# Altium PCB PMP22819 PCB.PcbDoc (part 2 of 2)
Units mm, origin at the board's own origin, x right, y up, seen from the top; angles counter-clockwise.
Board outline 101.6 x 76.2 mm, 4 copper layers (Top Layer, Mid-Layer 1, Mid-Layer 2, Bottom Layer), stack 2.286 mm thick; 108 components, 51 nets, 288 pads, 278 vias.
Unrouted connection lines stored in the file: 1.
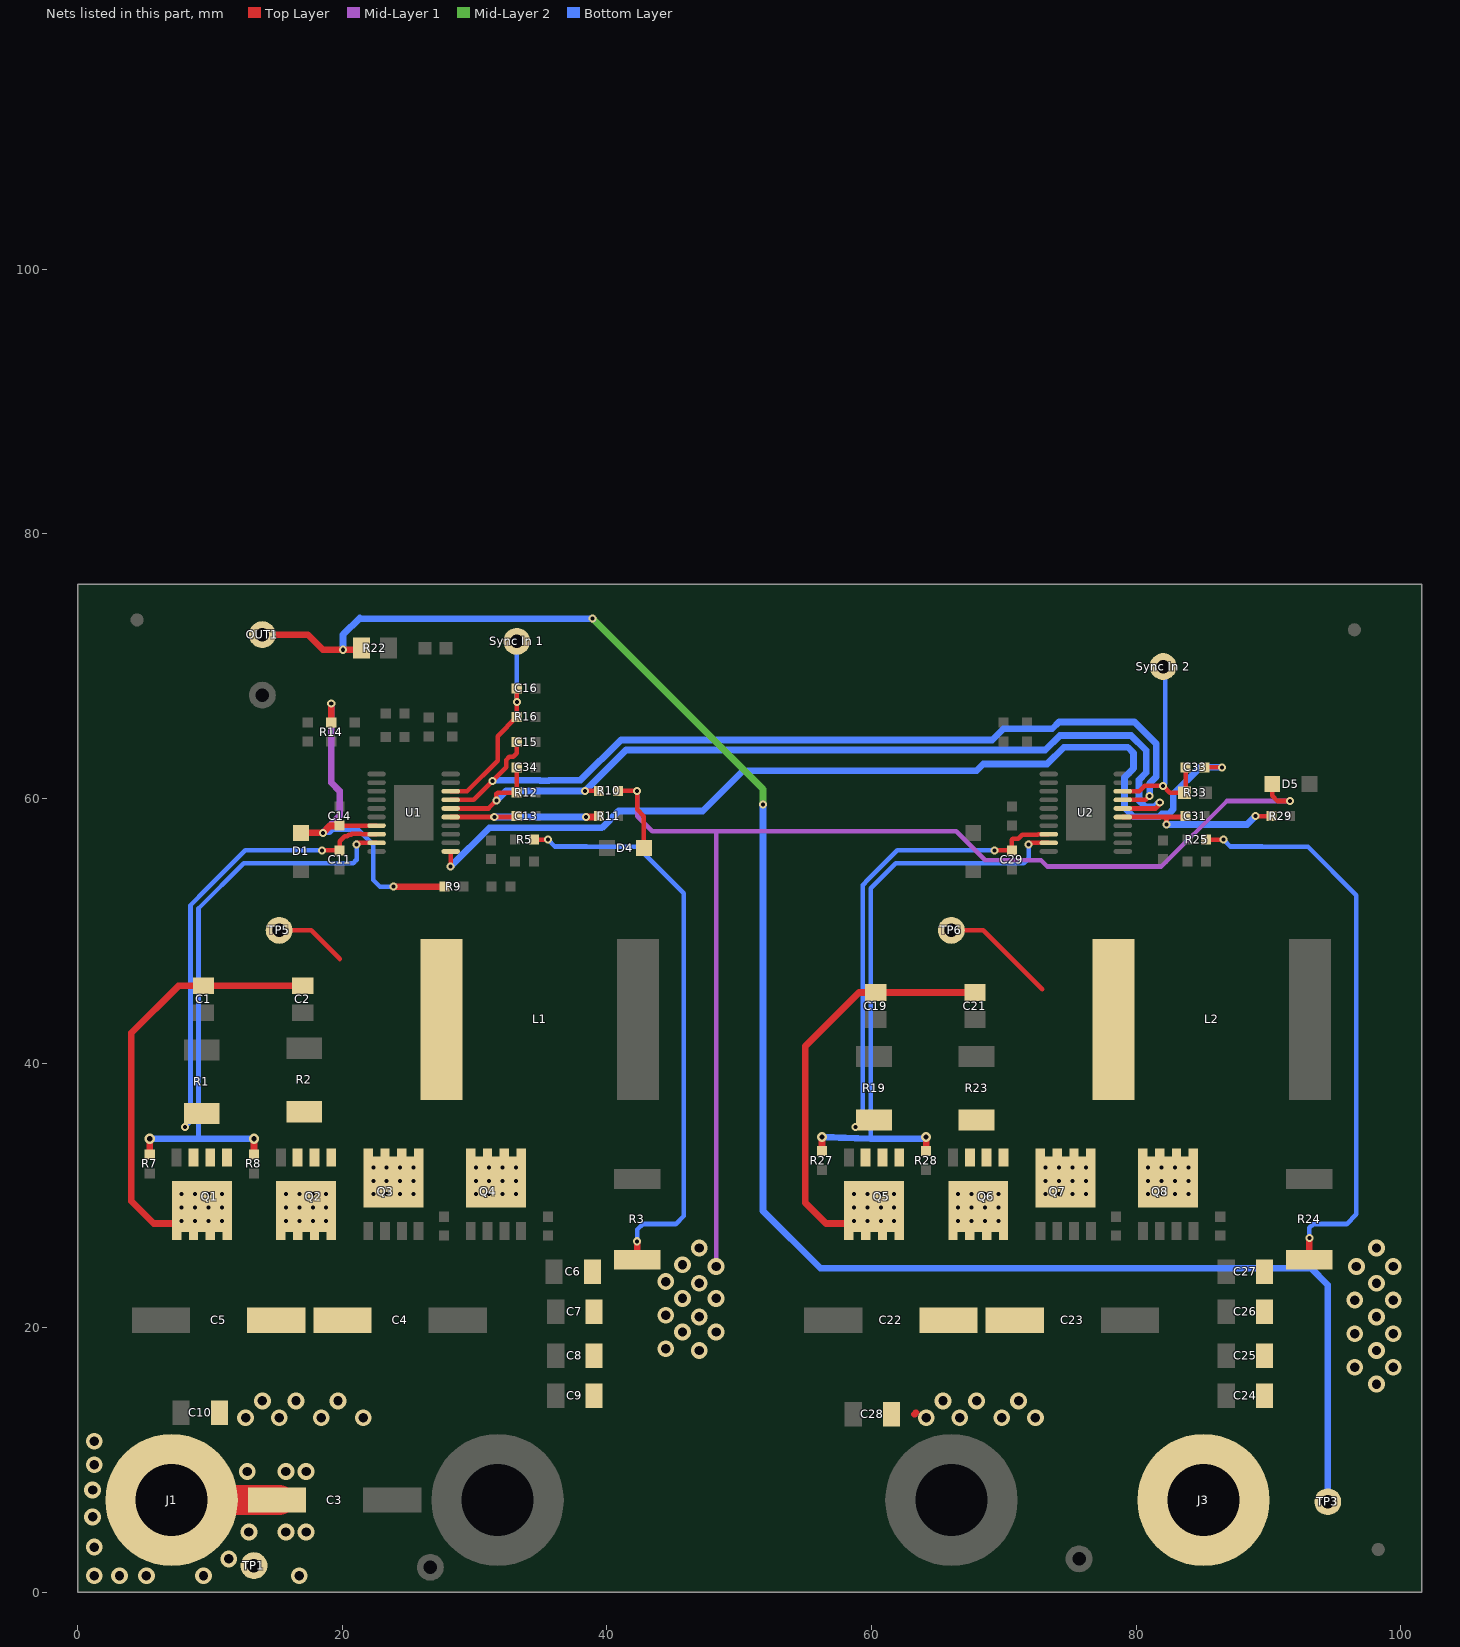
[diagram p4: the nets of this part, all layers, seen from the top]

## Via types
v1: diameter 0.61, hole 0.305, Top Layer to Bottom Layer, 169 vias
v2: diameter 1.27, hole 0.711, Top Layer to Bottom Layer, 101 vias
v3: diameter 0.762, hole 0.381, Top Layer to Bottom Layer, 8 vias

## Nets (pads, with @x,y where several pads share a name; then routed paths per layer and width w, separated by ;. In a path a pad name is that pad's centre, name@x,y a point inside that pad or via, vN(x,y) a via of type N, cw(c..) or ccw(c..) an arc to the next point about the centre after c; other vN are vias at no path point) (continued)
SS: C15.1 U1.7 U2.7 | length 66.6
  Top Layer w0.35: U1.7@28.2,59.903 29.931,59.903 v1(31.369,61.341) 32.388,62.36 32.388,62.916 32.639,63.167 32.941,63.167 33.198,63.424 C15.1@33.198,64.262 ; U2.7@79,59.903 80.731,59.903 v1(81.026,60.198)
  Bottom Layer w0.508: v1(31.369,61.341) 31.42,61.392 34.94,61.392 34.99,61.341 35.622,61.341 35.672,61.392 38.024,61.392 41.066,64.434 69.133,64.434 69.977,65.278 73.666,65.278 74.174,65.786 79.883,65.786 81.534,64.135 81.534,61.66 81.026,61.152 v1(81.026,60.198)
SW1_N: R7.2 R8.2 U1.19 | length 44
  Top Layer w0.35: v1(21.082,56.515) 21.082,56.642 21.093,56.653 U1.19@22.6,56.653
  Top Layer w0.508: R7.2@5.461,33.236 v3@5.461,34.302 ; R8.2@13.335,33.096 v3(13.335,34.29)
  Bottom Layer w0.35: 9.144,34.29 9.144,51.689 12.573,55.118 20.828,55.118 21.071,55.361 21.093,55.361 21.093,56.653 21.082,56.642 v1(21.082,56.515)
  Bottom Layer w0.508: v3(5.461,34.29) 9.144,34.29 ; 9.223,34.29 v3(13.335,34.29)
SW1_P: C11.1 L1.2 Q1.1 Q1.2 Q1.3 Q2.1 Q2.2 Q2.3 Q3.5 Q3.6 Q3.7 Q3.8 Q3.9 Q4.5 Q4.6 Q4.7 Q4.8 Q4.9 R1.2 R2.2 TP5.1 U1.18 | length 39.1
  Top Layer w0.35: TP5.1@15.24,50.038 17.653,50.038 19.812,47.879 ; v1(18.491,56.083) C11.1@19.812,56.083 19.812,56.769 20.196,57.153 20.371,57.153 20.495,57.277 20.679,57.277 20.738,57.336 21.448,57.336 21.481,57.303 U1.18@22.567,57.303
  Bottom Layer w0.35: v1(8.128,35.179) 8.54,35.591 8.54,51.939 9.733,53.132 12.684,56.083 v1(18.491,56.083)
  other v1: 22.352,30.099 23.368,30.099 24.384,30.099 25.4,30.099 30.099,30.099 31.115,30.099 32.131,30.099 33.147,30.099 22.352,31.115 23.368,31.115 24.384,31.115 25.4,31.115 30.099,31.115 31.115,31.115 32.131,31.115 33.147,31.115 22.352,32.131 23.368,32.131 24.384,32.131 25.4,32.131 30.099,32.131 31.115,32.131 32.131,32.131 33.147,32.131
SW2_N: R27.2 R28.2 U2.19 | length 44.6
  Top Layer w0.35: v1(71.882,56.515) 71.882,56.642 71.893,56.653 U2.19@73.4,56.653
  Top Layer w0.508: R27.2@56.261,33.35 v3(56.261,34.417) ; R28.2@64.135,33.35 v3(64.135,34.417)
  Bottom Layer w0.35: 59.944,34.29 59.944,49.959 59.944,53.213 61.849,55.118 71.501,55.118 71.882,55.499 v1(71.882,56.515) 71.882,56.642 v1@71.893,56.653
  Bottom Layer w0.508: v3(56.261,34.417) 59.944,34.29 v3@64.135,34.29
SW2_P: C29.1 L2.2 Q5.1 Q5.2 Q5.3 Q6.1 Q6.2 Q6.3 Q7.5 Q7.6 Q7.7 Q7.8 Q7.9 Q8.5 Q8.6 Q8.7 Q8.8 Q8.9 R19.2 R23.2 TP6.1 U2.18 | length 43.4
  Top Layer w0.35: TP6.1@66.04,50.038 68.453,50.038 72.898,45.593 ; v1(69.291,56.083) C29.1@70.612,56.083 70.612,56.896 70.687,56.971 71.105,56.971 71.399,57.265 72.558,57.265 72.596,57.303 U2.18@73.4,57.303
  Bottom Layer w0.35: v1(58.801,35.179) 59.34,35.718 59.34,53.463 59.771,53.894 61.96,56.083 v1(69.291,56.083) v1@69.367,56.007
  other v1: 73.152,30.099 74.168,30.099 75.184,30.099 76.2,30.099 80.899,30.099 81.915,30.099 82.931,30.099 83.947,30.099 73.152,31.115 74.168,31.115 75.184,31.115 76.2,31.115 80.899,31.115 81.915,31.115 82.931,31.115 83.947,31.115 73.152,32.131 74.168,32.131 75.184,32.131 76.2,32.131 80.899,32.131 81.915,32.131 82.931,32.131 83.947,32.131
SYN1: "Sync In 1.1" C16.2 R16.2 U1.8 | length 15.1
  Top Layer w0.35: U1.8@28.2,60.553 29.438,60.553 31.75,62.865 31.75,64.719 R16.2@33.198,66.167 C16.2@33.198,68.326
  Bottom Layer w0.35: v1(33.198,67.31) 33.198,71.882
SYN2: "Sync In 2.1" C33.2 R33.2 U2.8 | length 16.1
  Top Layer w0.35: U2.8@79,60.553 80.238,60.553 80.645,60.96 v1(82.042,60.96) 82.55,60.452 R33.2@83.655,60.452 83.744,60.541 C33.2@83.744,62.357
  Bottom Layer w0.35: v1(82.042,60.96) 82.217,61.135 82.217,69.802 82.042,69.977
"SYNC OUT1": C33.1 U1.1 | length 72.3
  Top Layer w0.35: v1(28.194,54.864) 28.194,55.997 U1.1@28.2,56.003 ; C33.1@85.166,62.357 v1(86.487,62.357)
  Bottom Layer w0.508: v1(28.194,54.864) 31.12,57.79 39.624,57.79 40.894,59.06 47.249,59.06 50.292,62.103 67.945,62.103 68.453,62.611 73.279,62.611 74.549,63.881 79.375,63.881 79.813,63.443 79.813,62.287 79.121,61.595 79.121,59.309 79.807,58.623 81.731,58.623 81.959,58.852 82.474,58.852 82.804,59.182 82.804,60.325 84.836,62.357 v1(86.487,62.357)
UVLO: C34.1 R10.1 R12.2 U1.6 U2.6 | length 69.1
  Top Layer w0.35: U1.6@28.2,59.253 31.059,59.253 v1(31.659,59.853) 31.659,60.361 31.75,60.452 R12.2@32.982,60.452 ; R12.2@33.198,60.452 C34.1@33.198,62.357 ; v1(38.354,60.579) R10.1@39.421,60.579 ; U2.6@79,59.253 81.478,59.253 81.788,59.563 v1(81.788,59.69)
  Bottom Layer w0.508: v1(31.659,59.853) 32.385,60.579 v1(38.354,60.579) 41.447,63.672 73.138,63.672 74.236,64.77 79.629,64.77 80.772,63.627 80.772,61.976 80.213,61.417 80.213,59.861 80.689,59.385 81.415,59.385 81.72,59.69 v1(81.788,59.69)
VCC: C14.1 D1.2 R9.2 R14.2 U1.17 | length 30.6
  Top Layer w0.35: C14.1@19.822,57.953 19.835,57.94 22.587,57.94 U1.17@22.6,57.953
  Top Layer w0.508: D1.2@16.891,57.407 18.539,57.407 19.05,57.918 19.767,57.918 C14.1@19.812,57.963 ; R14.2@19.177,65.735 v1(19.177,67.183) ; v1(23.876,53.34) R9.2@27.737,53.34
  Mid-Layer 1 w0.508: v1(18.542,57.404) 19.812,58.674 19.812,60.579 19.177,61.214 v1(19.177,67.183)
  Bottom Layer w0.35: v1(18.542,57.404) 19.05,57.404 19.304,57.658 21.209,57.658 22.352,56.515 22.352,53.848 22.86,53.34 v1(23.876,53.34)
VIN: C3.1 C6.1 C7.1 C8.1 C9.1 C24.1 C25.1 C26.1 C27.1 D4.2 D5.2 J1.1 R3.1 R5.2 R10.2 R24.1 R25.2 TP1.1 | length 191.6
  Top Layer w0.35: R5.2@34.493,56.896 v1(35.56,56.896) ; R10.2@40.843,60.579 v1(42.291,60.579) 42.291,59.182 42.802,58.671 D4.2@42.802,56.261 ; R25.2@85.293,56.896 v1(86.614,56.896) ; D5.2@90.294,61.087 90.294,60.201 90.678,59.817 v1(91.643,59.817)
  Top Layer w0.508: R3.1@42.291,25.144 v1(42.291,26.543) ; R24.1@93.091,25.144 v1(93.091,26.797)
  Top Layer w2.286: J1.1@7.112,6.985 C3.1@15.273,6.985
  Mid-Layer 1 w0.35: v1(42.291,60.579) 42.291,58.674 43.434,57.531 48.133,57.531 ; v2(48.26,24.638) 48.26,57.404 48.133,57.531 ; v1(91.643,59.817) 86.868,59.817 81.915,54.864 73.301,54.864 72.815,55.349 68.603,55.349 66.421,57.531 48.133,57.531
  Bottom Layer w0.35: v1(35.56,56.896) 36.083,56.373 38.477,56.373 38.493,56.357 42.287,56.357 45.816,52.828 45.816,28.452 45.208,27.844 42.703,27.844 42.291,27.432 v1(42.291,26.543) ; v1(86.614,56.896) 87.137,56.373 89.531,56.373 89.547,56.357 92.995,56.357 96.647,52.705 96.647,28.575 95.916,27.844 93.376,27.844 93.091,27.559 v1(93.091,26.797)
  other v2: 1.27,1.27 3.175,1.27 5.207,1.27 9.525,1.27 16.764,1.27 11.43,2.54 1.27,3.429 12.954,4.572 15.748,4.572 17.272,4.572 1.143,5.715 1.143,7.747 12.827,9.144 15.748,9.144 17.272,9.144 1.27,9.652 1.27,11.43 98.171,15.748 96.52,17.018 99.441,17.018 46.99,18.288 98.171,18.288 44.45,18.415 96.52,19.558 99.441,19.558 45.72,19.685 48.26,19.685 46.99,20.828 98.171,20.828 44.45,20.955 96.52,22.098 99.441,22.098 45.72,22.225 48.26,22.225 46.99,23.368 98.171,23.368 44.45,23.495 96.647,24.638 99.441,24.638 45.72,24.765 46.99,26.035 98.171,26.035
VIN1: C13.1 R11.1 U1.5 | length 12.7
  Top Layer w0.35: U1.5@28.2,58.603 v1(31.496,58.603) 32.873,58.603 C13.1@32.944,58.674
  Top Layer w0.508: v1(38.425,58.603) 39.35,58.603 R11.1@39.421,58.674
  Bottom Layer w0.508: v1(31.496,58.603) v1(38.425,58.603)
VIN2: C31.1 R29.1 U2.5 | length 13.5
  Top Layer w0.35: U2.5@79,58.603 82.296,58.603 ; v1(82.296,58.039) 82.296,58.603 ; C31.1@83.744,58.674 83.673,58.603 82.296,58.603 ; v1(89.027,58.674) R29.1@90.221,58.674
  Bottom Layer w0.508: v1(82.296,58.039) 88.392,58.039 v1(89.027,58.674)
VOUT: C1.1 C2.1 C4.1 C5.1 C10.1 C19.1 C21.1 C22.1 C23.1 C28.1 J3.1 OUT1.1 Q1.5 Q1.6 Q1.7 Q1.8 Q1.9 Q2.5 Q2.6 Q2.7 Q2.8 Q2.9 Q5.5 Q5.6 Q5.7 Q5.8 Q5.9 Q6.5 Q6.6 Q6.7 Q6.8 Q6.9 R22.1 TP3.1 | length 206.9
  Top Layer w0.508: Q1.9@10.16,27.89 5.765,27.89 4.064,29.591 4.064,42.291 7.62,45.847 C2.1@17.018,45.847 ; OUT1.1@13.97,72.39 17.399,72.39 18.542,71.247 v1(20.066,71.247) R22.1@21.336,71.247 ; Q5.9@60.96,27.89 56.565,27.89 54.991,29.464 54.991,41.275 59.055,45.339 C21.1@67.818,45.339 ; 63.246,13.462 63.373,13.589
  Mid-Layer 2 w0.508: v1(38.925,73.596) 51.813,60.709 v1(51.813,59.563)
  Bottom Layer w0.508: v1(20.066,71.247) 20.066,72.39 21.336,73.66 ; 21.336,73.596 v1(38.925,73.596) ; v1(51.813,59.563) 51.813,28.826 56.128,24.511 93.218,24.511 94.488,23.241 TP3.1@94.488,6.858
  other v1: 7.874,28.067 8.89,28.067 9.906,28.067 10.922,28.067 15.748,28.067 16.764,28.067 17.78,28.067 18.796,28.067 58.674,28.067 59.69,28.067 60.706,28.067 61.722,28.067 66.548,28.067 67.564,28.067 68.58,28.067 69.596,28.067 7.874,29.083 8.89,29.083 9.906,29.083 10.922,29.083 15.748,29.083 16.764,29.083 17.78,29.083 18.796,29.083 58.674,29.083 59.69,29.083 60.706,29.083 61.722,29.083 66.548,29.083 67.564,29.083 68.58,29.083 69.596,29.083 7.874,30.099 8.89,30.099 9.906,30.099 10.922,30.099 15.748,30.099 16.764,30.099 17.78,30.099 18.796,30.099 58.674,30.099 59.69,30.099 60.706,30.099 61.722,30.099 66.548,30.099 67.564,30.099 68.58,30.099 69.596,30.099
  other v2: 12.7,13.208 15.24,13.208 18.415,13.208 21.59,13.208 64.135,13.208 66.675,13.208 69.85,13.208 72.39,13.208 13.97,14.478 16.51,14.478 19.685,14.478 65.405,14.478 67.945,14.478 71.12,14.478
pads on no net: FID1.1 FID2.1 FID3.1 LBL1.0 Q1.0 Q2.0 Q3.0 Q4.0 Q5.0 Q6.0 Q7.0 Q8.0 U2.1

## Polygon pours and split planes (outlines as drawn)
GND on Top Layer "Top Layer-GND" (solid, remove dead copper, pour order 84): 44.958,76.835 44.958,70.739 14.478,70.739 14.478,49.911 11.176,46.609 9.271,46.609 4.826,42.164 4.826,27.051 0,27.051 -0.127,26.924 -0.127,76.327
GND on Top Layer "Top Layer-GND" (solid, remove dead copper, pour order 82): 16.129,65.278 16.129,68.072 18.161,70.104 38.608,70.104 38.608,52.578 32.258,52.578 32.258,53.848 36.576,53.848 36.576,58.039 33.909,58.039 33.909,67.31 32.639,67.31 32.639,65.151 31.877,64.389 31.877,63.627 29.337,61.087 29.083,61.087 29.083,65.659 27.686,65.659 27.686,67.31 21.717,67.31 21.717,65.278 20.32,65.278 20.32,67.945 18.161,67.945 17.907,67.691 17.907,65.278
GND on Top Layer "Top Layer-GND" (solid, remove dead copper, pour order 80): 21.336,27.937 21.336,25.141 22.86,23.617 22.86,-0.005 37.211,-0.005 37.211,25.908 32.639,25.908 32.639,27.938 29.337,27.943 29.337,25.908 24.892,25.908 24.892,27.941
CSN1_N on Top Layer "Top Layer-CSN1_N" (solid, remove dead copper, pour order 78): 40.259,49.403 40.259,30.48 44.577,30.48 44.577,49.403
SW1_P on Top Layer "Top Layer-SW1" (solid, remove dead copper, pour order 76): 33.909,49.911 33.909,29.083 20.066,29.083 20.066,32.131 8.382,32.131 8.382,33.909 7.62,33.909 7.62,39.37 18.923,39.37 18.923,49.911
VIN on Top Layer "Top Layer-VIN 6-8.4V" (solid, remove dead copper, pour order 74): 88.519,27.178 101.473,27.178 101.473,13.462 88.519,13.462
VIN on Top Layer "Top Layer-VIN 6-8.4V" (solid, remove dead copper, pour order 72): -0.127,12.319 -0.127,0 0,0.127 18.415,0.127 18.415,12.319
GND on Top Layer "Top Layer-GND" (solid, remove dead copper, pour order 70): 101.6,13.164 101.6,0.016 101.727,-0.127 19.05,-0.127 19.05,13.164
GND on Top Layer "Top Layer-No Net" (solid, remove dead copper, pour order 68): 71.247,65.278 71.247,67.564 88.138,67.564 88.138,58.293 88.265,58.166 84.709,58.166 84.709,60.96 87.122,60.96 87.122,63.119 83.566,63.119 81.661,61.214 80.772,61.214 79.756,61.087 79.756,64.516 79.121,65.278
VIN on Top Layer "Top Layer-VIN 6-8.4V" (solid, remove dead copper, pour order 66): 50.419,13.462 50.419,27.178 37.846,27.178 37.846,13.462
GND on Top Layer "Top Layer-GND" (solid, remove dead copper, pour order 64): 39.878,76.327 66.548,76.327 66.548,46.355 59.182,46.355 55.626,42.799 55.626,27.813 34.417,27.813 34.417,51.308 39.878,51.308
GND on Top Layer "Top Layer-GND" (solid, remove dead copper, pour order 62): 59.436,76.327 59.436,68.326 89.535,68.326 89.535,53.975 72.009,53.975 72.009,48.641 85.09,48.641 85.09,27.813 101.727,27.813 101.727,76.327
CSN2_N on Top Layer "Top Layer-CSN2_N" (solid, remove dead copper, pour order 60): 90.932,49.403 95.377,49.403 95.377,30.607 95.25,30.48 90.932,30.48
GND on Top Layer "Top Layer-GND" (solid, remove dead copper, pour order 58): 50.673,27.178 57.277,27.178 57.277,21.844 61.722,21.844 61.722,14.351 61.685,14.314 61.813,-0.127 50.673,-0.127
SW2_P on Top Layer "Top Layer-SW2" (solid, remove dead copper, pour order 56): 84.709,48.768 69.723,48.768 69.723,38.735 58.42,38.735 58.42,33.909 59.055,33.909 59.055,32.766 59.055,32.258 62.865,32.258 62.865,32.766 67.056,32.766 67.056,32.258 72.136,32.258 72.136,29.083 84.709,29.083
GND on Top Layer "Top Layer-GND" (solid, remove dead copper, pour order 54): 72.009,28.067 72.009,25.138 73.533,23.607 73.533,0 88.265,0 88.265,26.162 83.439,26.162 83.439,28.067 80.137,28.067 80.137,26.035 75.692,26.035 75.692,28.067
VOUT on Top Layer "Top Layer-VOUT +12V" (solid, remove dead copper, pour order 52): 57.912,31.115 70.612,31.115 70.612,25.019 71.628,25.019 73.279,23.368 73.279,12.446 61.976,12.446 61.976,22.098 57.912,22.098
GND on Top Layer "Top Layer-GND" (solid, remove dead copper, pour order 50): -0.127,25.908 6.477,25.908 6.477,23.876 9.779,20.574 9.779,12.827 -0.127,12.827
VOUT on Top Layer "Top Layer-VOUT" (solid, remove dead copper, pour order 48): 7.112,31.115 19.812,31.115 19.812,25.019 20.574,25.019 22.479,23.114 22.479,10.795 10.033,10.795 10.033,21.209 9.652,21.209 7.112,23.749
VIN on Mid-Layer 1 "MidLayer1-VIN 6-8.4V" (solid, remove dead copper, pour order 88): -0.127,-0.127 101.727,-0.127 101.727,46.99 -0.127,46.99
GND on Mid-Layer 1 "MidLayer1-GND" (solid, remove dead copper, pour order 86): 0,76.327 101.727,76.327 101.727,48.26 0,48.26
VOUT on Bottom Layer "Bottom Layer-VOUT +12V" (solid, remove dead copper, pour order 92): -0.254,0 101.727,0 101.854,-0.127 101.854,24.003 -0.122,24.003
GND on Bottom Layer "Bottom Layer-GND" (solid, remove dead copper, pour order 90): -0.127,76.327 101.6,76.327 101.6,23.368 -0.127,23.368
GND on Mid-Layer 2 "MidLayer2-GND" (solid, remove dead copper, pour order 94): 0,-0.635 101.6,-0.635 101.6,76.2 0,76.2

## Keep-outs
Keep-Out Layer:
  lines w0.254: -0.127,76.327 -0.127,-0.127 101.727,-0.127 101.727,76.327 0,76.327
  text ".Layer_Name" at 14.656,-21.806 h1.52

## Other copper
Top Layer:
  rectangle net GND: 23.876,55.118 26.924,63.246
  rectangle net GND: 74.676,54.991 77.724,62.865
  pour cut-out: 41.529,25.908 41.529,27.051 43.18,27.051 43.18,25.908
  pour cut-out: 92.329,27.305 93.98,27.305 93.98,26.162 92.329,26.162
  text ".Layer_Name" at 14.656,-21.806 h1.52
Mid-Layer 1:
  pour cut-out: 92.329,27.432 92.329,26.162 93.98,26.162 93.98,27.432
  pour cut-out: 41.529,27.178 43.18,27.178 43.18,25.908 41.529,25.908
Bottom Layer:
  pour cut-out: 94.869,7.747 94.869,22.479 94.107,22.479 94.107,7.747
  pour cut-out: 91.948,30.48 95.377,30.48 95.377,51.689 92.075,54.991 87.63,54.991 87.63,54.229 85.725,54.229 85.725,57.785 92.964,57.785 97.282,53.467 97.282,26.797 96.266,25.781 91.948,25.781
  pour cut-out: 34.671,57.658 34.671,54.61 36.957,54.61 36.957,55.118 41.656,55.118 44.577,52.197 44.577,30.734 41.402,30.734 41.402,25.654 43.053,25.654 43.942,26.543 46.228,26.543 46.482,26.797 46.482,53.213 42.672,57.023 36.957,57.023 36.957,57.658
  text ".Layer_Name" at 14.656,-21.806 h1.52

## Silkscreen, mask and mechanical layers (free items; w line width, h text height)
Top Overlay:
  text "'.PRJ_Number'.PCB_Rev" at 53.613,112.695 h2.75
  text ".Pcb_File_Name_No_Path" at 40.64,70.485 h1.52
  text "©" at 48.895,67.31 h2.67
  text ".CopyrightYear" at 51.435,67.31 h1.52
  text "SW" at 61.849,51.181 h1.02
  text "SW" at 10.922,51.054 h1.02
  text "VIN" at 10.922,10.541 h1.02
  text "GND" at 38.481,9.525 h1.52
  text "VOUT" at 91.313,9.398 h1.52
  text "GND" at 72.39,9.271 h1.52
  text ".Layer_Name" at 14.656,-21.806 h1.52
Bottom Overlay:
  text "MADE IN U.S." at 65.405,72.136 h1.52
  text "UL94V-0" at 78.486,72.009 h1.52
  text ".PCB_SilkRev" at 54.254,67.945 h1.52
  text ".PCB_CopperRev" at 58.826,67.945 h1.52
  text "-" at 60.325,67.945 h1.52
  text ".PRJ_BasePN" at 69.494,67.945 h1.52
  text "551" at 73.685,67.945 h1.52
  text ".Layer_Name" at 14.656,-21.806 h1.52
Top Paste:
  text ".Layer_Name" at 14.656,-21.806 h1.52
Bottom Paste:
  text ".Layer_Name" at 14.656,-21.806 h1.52
Top Solder:
  text ".Layer_Name" at 14.656,-21.806 h1.52
  text ".Layer_Name" at 14.656,-21.806 h1.52
Bottom Solder:
  text ".Layer_Name" at 14.656,-21.806 h1.52
Drill Guide:
  text ".Layer_Name" at 14.656,-21.806 h1.52
M1 Board Outline:
  the board outline again, w0.254
  text ".Layer_Name" at 14.656,-21.806 h1.52
M2 Board Dimensions:
  rectangle: 0,-6.985 3.175,-3.81
  rectangle: 3.175,-10.16 12.7,-6.985
  lines w0.178: 0,-6.985 25.4,-6.985 ; 3.175,-10.16 3.175,-3.81 ; 6.35,-10.16 6.35,-3.81 ; 12.7,-10.16 12.7,-3.81 ; 19.05,-10.16 19.05,-3.81 ; 0,-10.16 25.4,-10.16 25.4,-3.81 0,-3.81 0,-10.16
  text ".Layer_Name" at 14.656,-21.806 h1.52
M3 3D STEP Top:
  text ".Layer_Name" at 14.656,-21.806 h1.52
M4 3D STEP Bottom:
  text ".Layer_Name" at 14.656,-21.806 h1.52
M5 Assembly Top:
  lines w0.254: -7.417,-23.626 160.223,-23.626 ; -7.417,-18.462 160.274,-18.462 ; -7.417,-13.297 -7.417,-28.791 94.31,-28.791 160.274,-28.791 160.274,-13.297 -7.404,-13.297 -7.404,-28.791 32.614,-28.791 ; 55.194,-28.791 55.194,-13.297 ; 87.376,-18.462 87.376,-13.297 ; 108.712,-18.462 108.712,-13.297 ; 124.511,-28.956 124.511,-23.804
  text "COMPONENTS MARKED 'DNP' SHOULD NOT BE POPULATED." at 29.299,-8.09 h1.52
  text "ASSEMBLY VARIANT:" at 29.286,-11.024 h1.52
  text ".VariantName" at 55.601,-11.024 h1.52
  text "PCB VIEWED FROM TOP SIDE" at -5.804,-16.654 h1.52
  text "BOARD #:" at 57.099,-16.654 h1.52
  text ".PRJ_Number" at 70.955,-16.654 h1.52
  text "REV:" at 92.405,-16.654 h1.52
  text ".PCB_Rev" at 99.809,-16.654 h1.52
  text "SVN REV:" at 113.69,-16.654 h1.52
  text ".VersionControl_RevNumber" at 126.543,-16.654 h1.52
  text "TID #:" at 57.099,-21.819 h1.52
  text ".TID" at 70.955,-21.819 h1.52
  text "PLOT NAME =" at -5.804,-27.034 h1.52
  text ".plot_File_Name" at 14.656,-27.034 h1.52
  text "GENERATED    :" at 57.15,-27.034 h1.52
  text ".Print_Date" at 79.235,-27.034 h1.52
  text ".Print_Time" at 97.752,-27.034 h1.52
  text "TEXAS INSTRUMENTS" at 129.87,-27.034 h1.52
M6 Assembly Bottom:
  lines w0.254: -7.429,-18.474 160.261,-18.474 ; -7.379,-23.639 160.261,-23.639 ; 28.334,-28.969 28.334,-23.817 ; 44.133,-18.474 44.133,-13.31 ; 65.468,-18.474 65.468,-13.31 ; 97.65,-28.804 97.65,-13.31 ; 120.231,-28.804 160.249,-28.804 160.249,-13.31 -7.429,-13.31 -7.429,-28.804 58.534,-28.804 160.261,-28.804 160.261,-13.31
  text "COMPONENTS MARKED 'DNP' SHOULD NOT BE POPULATED." at 154.991,-8.077 h1.52
  text ".VariantName" at 128.473,-11.024 h1.52
  text "ASSEMBLY VARIANT:" at 154.864,-11.024 h1.52
  text ".VersionControl_RevNumber" at 26.302,-16.667 h1.52
  text "SVN REV:" at 39.154,-16.667 h1.52
  text ".PCB_Rev" at 53.035,-16.667 h1.52
  text "REV:" at 60.439,-16.667 h1.52
  text ".PRJ_Number" at 81.89,-16.667 h1.52
  text "BOARD #:" at 95.745,-16.667 h1.52
  text "PCB VIEWED FROM BOTTOM SIDE" at 158.648,-16.667 h1.52
  text ".TID" at 81.89,-21.831 h1.52
  text "TID #:" at 95.745,-21.831 h1.52
  text "TEXAS INSTRUMENTS" at 22.974,-27.047 h1.52
  text ".Print_Time" at 55.093,-27.047 h1.52
  text ".Print_Date" at 73.609,-27.047 h1.52
  text "GENERATED    :" at 95.694,-27.047 h1.52
  text ".plot_File_Name" at 138.189,-27.047 h1.52
  text "PLOT NAME =" at 158.648,-27.047 h1.52
M9 Title Sheet:
  drawing of 57 lines, arcs and shapes, not listed
  text "1" at 18.792,204.127 h1.78
  text "2" at 82.182,204.127 h1.78
  text "3" at 145.411,204.127 h1.78
  text "4" at 209.08,204.127 h1.78
  text "5" at 272.555,204.127 h1.78
  text "6" at 336.182,204.127 h1.78
  text "A" at -10.579,175.095 h1.78
  text "A" at 365.341,175.095 h1.78
  text "B" at -10.579,114.643 h1.78
  text "B" at 365.341,114.643 h1.78
  text "C" at -10.579,54.318 h1.78
  text "C" at 365.341,54.318 h1.78
  text "PROJECT TITLE:" at 288.125,7.048 h1.14
  text ".PRJ_Title" at 289.395,3.662 h1.78
  text "DESIGNED FOR:" at 288.125,-0.597 h1.14
  text ".PRJ_Customer" at 289.395,-4.153 h1.78
  text "D" at -10.579,-5.88 h1.78
  text "D" at 365.341,-5.88 h1.78
  text "FILE NAME:" at 288.125,-8.217 h1.14
  text ".PCB_File_Name_No_Path" at 289.395,-11.265 h1.78
  text "Texas Instruments (TI) and/or its licensors do not warrant the accuracy or completeness of this specification" at 161.9,-15.376 h1.14
  text "ENGINEER:" at 288.125,-15.583 h1.14
  text "LAYOUT BY:" at 326.352,-15.583 h1.14
  text "or any information contained therein. TI and/or its licensors do not warrant that this design will meet" at 160.757,-18.237 h1.14
  text ".PRJ_Engineer" at 289.395,-19.52 h1.78
  text ".PCB_Layout" at 327.635,-19.52 h1.78
  text "the specifications, will be suitable for your application or fit for any particular purpose, or will operate in" at 160.757,-21.099 h1.14
  text ".Layer_Name" at 14.656,-21.806 h1.52
  text "ALTIUM DESIGNER VERSION:" at 326.352,-23.457 h1.14
  text "an implementation. TI and/or its licensors do not warrant that the design is production worthy. You should" at 160.757,-23.961 h1.14
  text "completely validate and test your design implementation to confirm the system functionality for your application." at 161.9,-26.822 h1.14
  text ".print_Scale" at 289.395,-26.843 h1.78
  text ".Application_BuildNumber" at 327.635,-26.843 h1.78
  text "1" at 18.792,-32.093 h1.78
  text "2" at 82.182,-32.093 h1.78
  text "3" at 145.411,-32.093 h1.78
  text "4" at 209.08,-32.093 h1.78
  text "5" at 272.555,-32.093 h1.78
  text "6" at 336.182,-32.093 h1.78
M10 Fab Notes:
  drawing of 189 lines, arcs and shapes, not listed
  text "DESIGN INFORMATION" at 314.503,161.447 h1.52
  text "MIN. TRACK WIDTH:" at 298.131,158.091 h1.52
  text "8" at 325.976,158.091 h1.52
  text "MIL" at 329.907,158.091 h1.52
  text "MIN. CLEARANCE:" at 298.131,154.938 h1.52
  text "0.2" at 324.452,154.938 h1.52
  text "mm" at 329.907,154.938 h1.52
  text "MIN. VIA PAD SIZE:" at 298.131,151.785 h1.52
  text "24" at 325.214,151.785 h1.52
  text "MIL" at 329.907,151.785 h1.52
  text "0.05mm (2MIL)" at 315.784,148.486 h1.52
  text "MINIMUM ANNULAR RING" at 289.769,148.277 h1.52
  text "EXTERNAL" at 333.768,148.277 h1.52
  text "PER" at 294.849,145.48 h1.52
  text "IPC-D-275 CLASS 2 LEVEL C" at 300.437,145.48 h1.52
  text "MIL, HOLES" at 338.238,142.928 h1.52
  text "+/-" at 328.27,142.709 h1.52
  text "+/-" at 349.961,142.709 h1.52
  text "REGISTRATION TOLERANCES:" at 289.769,142.682 h1.52
  text "METAL" at 320.243,142.682 h1.52
  text "5" at 334.879,142.683 h1.52
  text "3" at 356.037,142.683 h1.52
  text "MIL" at 358.99,142.682 h1.52
  text "HOLE SIZE TOLERANCE (UNLESS OTHERWISE SPECIFIED):" at 289.769,140.185 h1.52
  text "+/-" at 349.961,140.112 h1.52
  text "3" at 356.037,140.085 h1.52
  text "MIL" at 358.99,140.085 h1.52
  text "MATERIAL:" at 287.87,136.589 h1.52
  text "FR-4 High Tg" at 312.926,133.324 h1.52
  text "X" at 309.257,133.122 h1.52
  text "FR-408" at 298.563,133.007 h1.52
  text "OTHER" at 336.358,133.007 h1.52
  text "62 MIL (1.6mm) +/-10%" at 306.694,129.374 h1.52
  text "X" at 303.643,129.312 h1.52
  text "THICKNESS:" at 289.769,129.165 h1.52
  text "OTHER" at 339.33,129.165 h1.52
  text "TOLERANCE:" at 289.769,125.652 h1.52
  text "X" at 311.314,125.652 h1.52
  text "ANSI IPC-6012 TYPE 3 CLASS 2" at 315.836,125.652 h1.52
  text "OTHER +/-" at 315.835,121.989 h1.52
  text "BOW & TWIST:" at 289.769,118.302 h1.52
  text "X" at 311.314,118.302 h1.52
  text "ANSI IPC-6012 TYPE 3 CLASS 2" at 315.836,118.302 h1.52
  text "OTHER +/-" at 315.835,114.576 h1.52
  text "DRILLING:" at 287.87,111.258 h1.52
  text "NC_DRILL FILES" at 332.599,108.586 h1.52
  text "REFERENCE:" at 289.769,108.486 h1.52
  text "X" at 306.463,108.484 h1.52
  text "AS SHOWN" at 310.984,108.486 h1.52
  text "X" at 329.348,108.486 h1.52
  text "OTHER" at 340.168,104.873 h1.52
  text "PTH COPPER THICKNESS:" at 289.761,104.783 h1.52
  text "X" at 318.697,104.783 h1.52
  text "20-30 um" at 321.948,104.783 h1.52
  text "BOARD FINISH:" at 287.87,101.034 h1.52
  text "SILKSCREEN:" at 291.812,98.237 h1.52
  text "X" at 316.14,98.237 h1.52
  text "TOP" at 319.112,98.237 h1.52
  text "X" at 329.094,98.237 h1.52
  text "BOTTOM" at 332.091,98.237 h1.52
  text "SILKSCREEN COLOR:" at 291.812,94.295 h1.52
  text "X" at 316.115,94.295 h1.52
  text "WHITE" at 319.112,94.295 h1.52
  text "OTHER" at 332.091,94.295 h1.52
  text "X" at 319.442,90.652 h1.52
  text "GREEN" at 322.439,90.652 h1.52
  text "OTHER" at 338.136,90.652 h1.52
  text "SOLDER RESIST COLOR:" at 291.812,90.477 h1.52
  text "X" at 319.442,86.734 h1.52
  text "MATTE" at 322.439,86.734 h1.52
  text "SEMI-GLOSS" at 338.125,86.717 h1.52
  text "IMMERSION GOLD (ENIG)" at 314.819,82.345 h1.52
  text "ENEPIG" at 348.793,82.162 h1.52
  text "SURFACE FINISH:" at 287.87,82.136 h1.52
  text "X" at 310.298,82.136 h1.52
  text "IMM. TIN/SILVER OR EQUIV" at 296.24,78.649 h1.52
  text "OTHER" at 332.599,78.549 h1.52
  text "ARRAY/PANEL:" at 287.87,74.602 h1.52
  text "CUT AND TRIM PER M1 BOARD OUTLINE" at 314.819,74.393 h1.52
  text "N.C. ROUTE" at 314.819,70.94 h1.52
  text "X" at 332.295,70.94 h1.52
  text "V. SCORE" at 336.816,70.94 h1.52
  text "CERTIFICATION:" at 287.87,67.66 h1.52
  text "MATERIALS AND WORKMANSHIP FOR ALL PCBS" at 306.285,67.66 h1.52
  text "TO MEET OR EXCEED THE REQUIREMENTS OF:" at 306.285,65.271 h1.52
  text "X" at 297.078,62.003 h1.52
  text "ANSI IPC-A-600F CLASS ->" at 300.329,62.003 h1.52
  text "X" at 342.188,62.003 h1.52
  text "2" at 344.982,62.003 h1.52
  text "1" at 336.981,61.965 h1.52
  text "3" at 353.973,61.965 h1.52
  text "X" at 317.702,58.252 h1.52
  text "RoHS" at 320.953,58.252 h1.52
  text "OTHER" at 337.321,58.252 h1.52
  text "PER ORDER" at 347.407,58.252 h1.52
  text "ALL BOARDS MUST MEET OR EXCEED UL94-V0 REQUIREMENTS." at 288.569,54.345 h1.52
  text "PCB MUST BEAR THE UL94V-0 UL REGISTERED MATERIAL ID NUMBER" at 288.569,51.397 h1.52
  text "ADDITIONAL REQUIREMENTS:" at 287.87,47.094 h1.52
  text "MICROSECTION:" at 289.769,44.373 h1.52
  text "YES" at 312.775,44.373 h1.52
  text "REQUIRED" at 334.657,40.707 h1.52
  text "BARE BOARD ELEC. TEST:" at 289.769,40.634 h1.52
  text "NONE" at 322.935,40.634 h1.52
  text "X" at 331.66,40.634 h1.52
  text "PER ORDER" at 349.693,40.634 h1.52
  text "XX MIL VIAS REQUIRE NON-CONDUCTIVE FILL AND PLANARIZE" at 294.04,35.428 h1.5
  text "XX MIL VIAS REQUIRE CONDUCTIVE FILL AND PLANARIZE" at 294.243,32.787 h1.52
  text "OUTER XX MIL TRACES REQUIRE 50 OHM SINGLE-ENDED IMPEDANCE" at 294.218,28.637 h1.47
  text "LAYER 2 & 3 (INNER LAYERS) XX MIL WIDE, XX MIL SPACE / TRACES REQUIRE 100 OHM DIFFERENTIAL IMPEDANCE" at 294.015,22.65 h1.52
  text ".Layer_Name" at 14.656,-21.806 h1.52
M11 Gerber Information:
  lines w0.254: -7.417,-23.626 160.223,-23.626 ; -7.417,-18.462 160.274,-18.462 ; -7.417,-13.297 -7.417,-28.791 94.31,-28.791 160.274,-28.791 160.274,-13.297 -7.404,-13.297 -7.404,-28.791 32.614,-28.791 ; 55.194,-28.791 55.194,-13.297 ; 87.376,-18.462 87.376,-13.297 ; 108.712,-18.462 108.712,-13.297 ; 124.511,-28.956 124.511,-23.804
  text "ALL ARTWORK VIEWED FROM TOP SIDE" at -5.804,-16.654 h1.52
  text "BOARD #:" at 57.099,-16.654 h1.52
  text ".PRJ_Number" at 70.955,-16.654 h1.52
  text "REV:" at 92.405,-16.654 h1.52
  text ".PCB_Rev" at 99.809,-16.654 h1.52
  text "SVN REV:" at 113.69,-16.654 h1.52
  text ".VersionControl_RevNumber" at 126.543,-16.654 h1.52
  text "LAYER NAME =" at -5.804,-21.806 h1.52
  text "TID #:" at 57.099,-21.819 h1.52
  text ".TID" at 70.955,-21.819 h1.52
  text "PLOT NAME =" at -5.804,-27.034 h1.52
  text ".plot_File_Name" at 14.656,-27.034 h1.52
  text "GENERATED    :" at 57.15,-27.034 h1.52
  text ".Print_Date" at 79.235,-27.034 h1.52
  text ".Print_Time" at 97.752,-27.034 h1.52
  text "TEXAS INSTRUMENTS" at 129.87,-27.034 h1.52
M12 Stackup:
  drawing of 295 lines, arcs and shapes, not listed
  text "Layer" at 249.215,198.88 h1.52
  text "Name" at 259.626,198.88 h1.52
  text "Material" at 283.242,198.88 h1.52
  text "Thickness" at 305.08,198.88 h1.52
  text "Constant" at 321.586,198.88 h1.52
  text "Board Layer Stack" at 336.06,198.88 h1.52
  text "1" at 249.215,195.832 h1.52
  text "Top Overlay" at 259.626,195.832 h1.52
  text "2" at 249.215,192.784 h1.52
  text "Top Solder" at 259.626,192.784 h1.52
  text "Solder Resist" at 283.242,192.784 h1.52
  text "0.40mil" at 305.08,192.784 h1.52
  text "3.5" at 321.586,192.784 h1.52
  text "3" at 249.215,189.736 h1.52
  text "Top Layer" at 259.626,189.736 h1.52
  text "Copper" at 283.242,189.736 h1.52
  text "1.40mil" at 305.08,189.736 h1.52
  text "4" at 249.215,186.688 h1.52
  text "Dielectric1" at 259.626,186.688 h1.52
  text "FR-4" at 283.242,186.688 h1.52
  text "59.20mil" at 305.08,186.688 h1.52
  text "4.8" at 321.586,186.688 h1.52
  text "5" at 249.215,183.64 h1.52
  text "Mid-Layer 1" at 259.626,183.64 h1.52
  text "Copper" at 283.242,183.64 h1.52
  text "1.40mil" at 305.08,183.64 h1.52
  text "6" at 249.215,180.592 h1.52
  text "Dielectric2" at 259.626,180.592 h1.52
  text "FR-4" at 283.242,180.592 h1.52
  text "12.60mil" at 305.08,180.592 h1.52
  text "4.8" at 321.586,180.592 h1.52
  text "7" at 249.215,177.544 h1.52
  text "Mid-Layer 2" at 259.626,177.544 h1.52
  text "Copper" at 283.242,177.544 h1.52
  text "1.40mil" at 305.08,177.544 h1.52
  text "8" at 249.215,174.496 h1.52
  text "Dielectric3" at 259.626,174.496 h1.52
  text "FR-4" at 283.242,174.496 h1.52
  text "12.60mil" at 305.08,174.496 h1.52
  text "4.8" at 321.586,174.496 h1.52
  text "9" at 249.215,171.448 h1.52
  text "Bottom Layer" at 259.626,171.448 h1.52
  text "Copper" at 283.242,171.448 h1.52
  text "1.40mil" at 305.08,171.448 h1.52
  text "10" at 249.215,168.4 h1.52
  text "Bottom Solder" at 259.626,168.4 h1.52
  text "Solder Resist" at 283.242,168.4 h1.52
  text "0.40mil" at 305.08,168.4 h1.52
  text "3.5" at 321.586,168.4 h1.52
  text "11" at 249.215,165.352 h1.52
  text "Bottom Overlay" at 259.626,165.352 h1.52
  text ".Layer_Name" at 14.656,-21.806 h1.52
M13 Component Bodies Top:
  text ".Layer_Name" at 14.656,-21.806 h1.52
M14 Component Bodies Bottom:
  text ".Layer_Name" at 14.656,-21.806 h1.52
M15 Courtyards Top:
  text ".Layer_Name" at 14.656,-21.806 h1.52
M16 Courtyards Bottom:
  text ".Layer_Name" at 14.656,-21.806 h1.52
Drill Drawing:
  lines w0.254: 135.537,70.545 136.94,70.545 136.94,71.949 135.537,71.949 135.537,70.545 ; 135.537,75.107 136.94,75.107 136.238,73.703 135.537,75.107 ; 135.537,77.212 135.888,77.212 135.888,76.861 136.589,76.861 136.589,77.212 136.94,77.212 136.94,77.913 136.589,77.913 136.589,78.264 135.888,78.264 135.888,77.913 135.537,77.913 135.537,77.212 ; 135.537,80.019 136.238,80.369 136.94,80.019 136.589,80.72 136.94,81.422 136.238,81.071 135.537,81.422 135.888,80.72 135.537,80.019 ; 135.537,83.527 135.888,83.527 136.238,83.176 136.589,83.527 136.94,83.527 136.589,83.878 136.94,84.229 136.589,84.229 136.238,84.58 135.888,84.229 135.537,84.229 135.888,83.878 135.537,83.527
  lines w0.305: 134.264,69.598 216.344,69.598 ; 134.264,85.387 216.344,85.387 ; 142.846,66.44 142.846,88.544 ; 151.279,66.44 151.279,88.544 ; 167.448,66.44 167.448,88.544 ; 174.03,66.44 174.03,88.544 ; 183.559,66.44 183.559,88.544 ; 201.957,66.44 201.957,88.544 ; 134.264,66.44 216.344,66.44 216.344,88.544 134.264,88.544 134.264,66.44
  text "Symbol" at 136.159,86.334 h1.83
  text "Quantity" at 143.793,86.334 h1.83
  text "Finished Hole Size" at 152.226,86.334 h1.83
  text "Plated" at 168.395,86.334 h1.83
  text "Hole Type" at 174.977,86.334 h1.83
  text "Drill Layer Pair" at 184.506,86.334 h1.83
  text "Hole Tolerance" at 202.904,86.334 h1.83
  text "169" at 143.793,83.176 h1.52
  text "12.00mil (0.305mm)" at 152.226,83.176 h1.52
  text "PTH" at 168.395,83.176 h1.52
  text "Round" at 174.977,83.176 h1.52
  text "Top Layer - Bottom Layer" at 184.506,83.176 h1.52
  text "8" at 143.793,80.019 h1.52
  text "15.00mil (0.381mm)" at 152.226,80.019 h1.52
  text "PTH" at 168.395,80.019 h1.52
  text "Round" at 174.977,80.019 h1.52
  text "Top Layer - Bottom Layer" at 184.506,80.019 h1.52
  text "101" at 143.793,76.861 h1.52
  text "28.00mil (0.711mm)" at 152.226,76.861 h1.52
  text "PTH" at 168.395,76.861 h1.52
  text "Round" at 174.977,76.861 h1.52
  text "Top Layer - Bottom Layer" at 184.506,76.861 h1.52
  text "10" at 143.793,73.703 h1.52
  text "40.00mil (1.016mm)" at 152.226,73.703 h1.52
  text "PTH" at 168.395,73.703 h1.52
  text "Round" at 174.977,73.703 h1.52
  text "Top Layer - Bottom Layer" at 184.506,73.703 h1.52
  text "4" at 143.793,70.545 h1.52
  text "214.57mil (5.450mm)" at 152.226,70.545 h1.52
  text "PTH" at 168.395,70.545 h1.52
  text "Round" at 174.977,70.545 h1.52
  text "Top Layer - Bottom Layer" at 184.506,70.545 h1.52
  text "292 Total" at 143.793,67.388 h1.52
  text ".Layer_Name" at 14.656,-21.806 h1.52
M17 Embedded Cavity:
  text ".Layer_Name" at 14.656,-21.806 h1.52
M18 Embedded Assembly:
  text ".Layer_Name" at 14.656,-21.806 h1.52
M19 Embedded Keepout:
  text ".Layer_Name" at 14.656,-21.806 h1.52

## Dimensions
0,-10.16 to 25.4,-10.16 on M2 Board Dimensions
0,0 to 0,76.2 on M2 Board Dimensions
0,0 to 101.6,0 on M2 Board Dimensions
